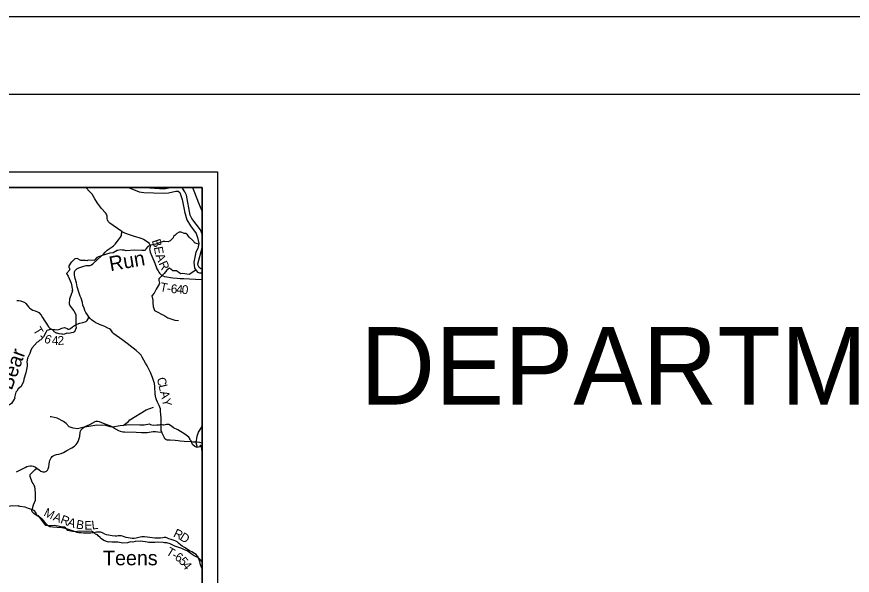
# Model space of a CAD drawing. Extents: x -1.8 to 75.7, y -2 to 25.
# Drawn here: x 7.7 to 13.09, y 18.4 to 22 of the extents above; entities that cross this region are included whole.
import ezdxf

# ---------------------------------------------------------------- set-up
doc = ezdxf.new("R2010")
doc.units = 0
for name, color, linetype in [('GM_X_County_Road', 7, 'Continuous'), ('GM_X_County_Road_Text', 7, 'Continuous'), ('GM_X_Major_River', 7, 'Continuous'), ('GM_X_Minor_River', 7, 'Continuous'), ('GM_X_Minor_River_Text', 7, 'Continuous'), ('GM_X_Township', 7, 'Continuous'), ('GM_X_Township_Road', 7, 'Continuous'), ('GM_X_Township_Road_Text', 7, 'Continuous'), ('SH_Border', 7, 'Continuous'), ('SH_Cut_Line', 7, 'Continuous'), ('SH_Data', 7, 'Continuous'), ('SH_Text', 7, 'Continuous')]:
    doc.layers.add(name, color=color, linetype=linetype)

msp = doc.modelspace()

# ---------------------------------------------------------------- linework, layer by layer
at = {"layer": 'GM_X_County_Road'}
for points in [[(8.6129, 19.5164), (8.6055, 19.5311), (8.6015, 19.5441), (8.599, 19.5551), (8.5975, 19.5698), (8.5969, 19.5817), (8.5961, 19.5989), (8.5961, 19.6158), (8.5931, 19.6351), (8.5804, 19.6748), (8.567, 19.7056), (8.5546, 19.7315), (8.5457, 19.7493), (8.5358, 19.7661), (8.5235, 19.7862), (8.5134, 19.806), (8.5065, 19.8173), (8.4965, 19.8297), (8.4756, 19.8483), (8.4163, 19.8946), (8.383, 19.9184), (8.3303, 19.9552), (8.3234, 19.9619), (8.3167, 19.9743), (8.3109, 19.9823), (8.3031, 19.9873), (8.2914, 19.9932), (8.2725, 20.0039), (8.2629, 20.0084), (8.2489, 20.0124), (8.2339, 20.018), (8.214, 20.0275), (8.2016, 20.0354), (8.187, 20.0465), (8.1786, 20.0544), (8.1698, 20.0651), (8.1612, 20.0781), (8.151, 20.0932), (8.1444, 20.1069), (8.139, 20.1218), (8.1318, 20.1417), (8.1296, 20.1583), (8.1206, 20.1847), (8.1145, 20.199), (8.1076, 20.2178), (8.0953, 20.2593), (8.0896, 20.2853), (8.0818, 20.3129), (8.0767, 20.3333), (8.0762, 20.3451), (8.0771, 20.3549), (8.0795, 20.3612), (8.0855, 20.3692), (8.0924, 20.3754), (8.105, 20.3804), (8.1372, 20.391), (8.1534, 20.3953), (8.1684, 20.3953), (8.1789, 20.3966), (8.1878, 20.4001), (8.1963, 20.407), (8.2252, 20.4344), (8.2635, 20.4703), (8.2756, 20.482), (8.2879, 20.4944), (8.3011, 20.5028), (8.3204, 20.5164), (8.3292, 20.5229), (8.3388, 20.5335), (8.3614, 20.5614), (8.3733, 20.5785), (8.3792, 20.5904), (8.3811, 20.5997), (8.3814, 20.6066), (8.3829, 20.6148), (8.3263, 20.6539), (8.3057, 20.6698), (8.2946, 20.6794), (8.2898, 20.6899), (8.2881, 20.6987), (8.2878, 20.7144), (8.2835, 20.7269), (8.2774, 20.7366), (8.2503, 20.7632), (8.2247, 20.7987), (8.2092, 20.8253), (8.1901, 20.8555), (8.1759, 20.8717), (8.1492, 20.8981), (8.1462, 20.9)], [(8.8374, 20.9), (8.8501, 20.8661), (8.8768, 20.801), (8.8876, 20.7751), (8.9, 20.7454)], [(8.6394, 19.3214), (8.6367, 19.3321), (8.6365, 19.345), (8.6371, 19.3758), (8.6371, 19.3978), (8.6363, 19.4149), (8.6342, 19.434), (8.6319, 19.4605), (8.631, 19.4721), (8.6285, 19.4834), (8.6239, 19.4945), (8.613, 19.5162), (8.6129, 19.5164)], [(8.9, 19.252), (8.8855, 19.2557), (8.8673, 19.2572), (8.8418, 19.2583), (8.8323, 19.2588), (8.7846, 19.2614), (8.7578, 19.2639), (8.7448, 19.2656), (8.726, 19.2675), (8.6935, 19.2695), (8.6826, 19.2698), (8.675, 19.2704), (8.6703, 19.272), (8.6652, 19.2749), (8.6602, 19.2798), (8.6573, 19.2858), (8.6518, 19.2992), (8.6479, 19.3076), (8.6428, 19.3152), (8.6394, 19.3214)]]:
    msp.add_lwpolyline(points, dxfattribs=at)
at = {"layer": 'GM_X_Major_River'}
msp.add_line((8.879, 20.5392), (8.8731, 20.5069), dxfattribs=at)
for points in [[(8.4305, 20.9), (8.4357, 20.8947), (8.4948, 20.8711), (8.5244, 20.8667), (8.6492, 20.8622)], [(8.6965, 20.9), (8.6834, 20.895), (8.6562, 20.888), (8.5635, 20.8954), (8.5137, 20.9)], [(8.6492, 20.8622), (8.6828, 20.865), (8.7304, 20.8759), (8.7448, 20.876), (8.7573, 20.867), (8.7708, 20.8211), (8.784, 20.7583), (8.7871, 20.7442), (8.8025, 20.6916), (8.8254, 20.6527), (8.8628, 20.602), (8.8701, 20.5763), (8.879, 20.5392)], [(8.9, 20.5978), (8.8999, 20.5985), (8.8887, 20.6253), (8.8331, 20.699), (8.8224, 20.7205), (8.7998, 20.8498), (8.7898, 20.8721), (8.7738, 20.894), (8.764, 20.9)], [(8.8731, 20.5069), (8.86, 20.4829), (8.846, 20.4172), (8.8507, 20.38), (8.8698, 20.3544), (8.8827, 20.3491), (8.8955, 20.3496), (8.9, 20.3501)], [(8.9, 20.3751), (8.8916, 20.3753), (8.881, 20.3844), (8.8749, 20.3957), (8.8733, 20.4079), (8.9, 20.5102)]]:
    msp.add_lwpolyline(points, dxfattribs=at)
at = {"layer": 'GM_X_Minor_River'}
for points in [[(8.8781, 20.5341), (8.8615, 20.5388), (8.8581, 20.5426), (8.8562, 20.5407), (8.8384, 20.5593), (8.8173, 20.5779), (8.8063, 20.593), (8.7957, 20.6036), (8.7843, 20.6036), (8.7658, 20.6112), (8.7522, 20.6108), (8.7363, 20.6035), (8.7269, 20.5925), (8.7152, 20.5837), (8.7129, 20.5753), (8.6956, 20.557), (8.694, 20.5551), (8.6804, 20.5479), (8.6596, 20.5516), (8.6491, 20.5501), (8.6011, 20.5336), (8.5697, 20.5282), (8.5497, 20.5179), (8.5387, 20.5065), (8.5319, 20.4936), (8.5115, 20.4931), (8.4631, 20.4953), (8.4098, 20.4899), (8.3981, 20.4955), (8.3841, 20.4948), (8.375, 20.4974), (8.3558, 20.4939), (8.3524, 20.4932), (8.3267, 20.4787), (8.3059, 20.4752), (8.256, 20.4599), (8.2209, 20.448), (8.2088, 20.4339), (8.2031, 20.4278), (8.1653, 20.4312), (8.1562, 20.4273), (8.1475, 20.4281), (8.1173, 20.4291), (8.0938, 20.4405), (8.0795, 20.4397), (8.0572, 20.4184), (8.0546, 20.4168), (8.0406, 20.3948), (8.041, 20.3834), (8.044, 20.3792), (8.0459, 20.3655), (8.0263, 20.3449), (8.0357, 20.3278), (8.0547, 20.2823), (8.0638, 20.2363), (8.0604, 20.2325), (8.0638, 20.2336), (8.0544, 20.2032), (8.0453, 20.1808), (8.0427, 20.1515), (8.0431, 20.1492), (8.0495, 20.134), (8.0738, 20.1048), (8.0866, 20.0801), (8.0866, 20.0554), (8.0863, 20.0064), (8.0871, 19.9954), (8.0769, 19.9684), (8.0675, 19.9649), (8.0391, 19.9588), (8.0274, 19.9595), (8.0127, 19.9545), (8.0002, 19.9518), (7.9987, 19.9545), (7.9775, 19.9552), (7.9658, 19.9601), (7.9609, 19.9605), (7.945, 19.9692), (7.9446, 19.973), (7.9321, 19.9829), (7.9234, 19.9847), (7.8996, 19.9778), (7.8913, 19.9641), (7.8777, 19.9364), (7.86, 19.9181), (7.8535, 19.9154), (7.8422, 19.9036), (7.8358, 19.9017), (7.8192, 19.8834), (7.8014, 19.8624), (7.7931, 19.8449), (7.7924, 19.8427), (7.7894, 19.8286), (7.7743, 19.7997), (7.7697, 19.7749), (7.7724, 19.7609), (7.7709, 19.7483), (7.763, 19.7042), (7.7498, 19.6628), (7.7476, 19.6487), (7.7329, 19.6164)], [(8.8606, 20.3667), (8.8168, 20.3392), (8.7738, 20.3443), (8.7632, 20.3416), (8.758, 20.3448), (8.7355, 20.3626), (8.7105, 20.3619), (8.6902, 20.3785), (8.6853, 20.3779), (8.6721, 20.3673), (8.6548, 20.3447), (8.6209, 20.3109), (8.6202, 20.2999), (8.6253, 20.2826), (8.6239, 20.2751), (8.6034, 20.2446), (8.6009, 20.2393), (8.5905, 20.2188), (8.5763, 20.2014), (8.5827, 20.1735), (8.5825, 20.1556), (8.5837, 20.1317), (8.5939, 20.1067), (8.6605, 20.0722), (8.6794, 20.0584), (8.7235, 20.044), (8.7473, 20.0418)], [(7.7329, 19.6164), (7.714, 19.6003), (7.7057, 19.5866), (7.6996, 19.5805), (7.6894, 19.5463), (7.6913, 19.5368), (7.6891, 19.5364), (7.6887, 19.5345), (7.6706, 19.5071), (7.6585, 19.498), (7.6264, 19.4952), (7.6169, 19.491), (7.5984, 19.4876), (7.5791, 19.4906), (7.5663, 19.4886), (7.5447, 19.4821)], [(8.392, 19.3653), (8.4259, 19.3897), (8.4331, 19.4024), (8.5389, 19.4659), (8.5859, 19.483)], [(8.3714, 19.3637), (8.3227, 19.3535), (8.3077, 19.3555), (8.2793, 19.3659), (8.2222, 19.3678), (8.1314, 19.3513), (8.0964, 19.3437), (8.0678, 19.3476), (8.0431, 19.3564), (8.0225, 19.3768), (8.0063, 19.3906), (7.9651, 19.4132), (7.9259, 19.4198), (7.92, 19.4203)], [(8.9, 19.2049), (8.898, 19.2055), (8.8987, 19.2085), (8.8991, 19.2161), (8.8915, 19.2362), (8.8866, 19.2355), (8.8847, 19.2309), (8.8832, 19.2282), (8.8677, 19.2233), (8.8537, 19.2293), (8.8371, 19.2422), (8.8295, 19.2661), (8.8219, 19.2737), (8.8215, 19.2802), (8.8147, 19.2897), (8.7882, 19.309), (8.7432, 19.3363), (8.7167, 19.3495), (8.7031, 19.3601), (8.685, 19.3715), (8.6714, 19.3714), (8.654, 19.3668), (8.6513, 19.3676), (8.6351, 19.3714), (8.6233, 19.3671), (8.6086, 19.3679), (8.5855, 19.3659), (8.5682, 19.3701), (8.5602, 19.3735), (8.5273, 19.3669), (8.4982, 19.3665), (8.4336, 19.3686), (8.3707, 19.3635)], [(8.8694, 19.2238), (8.8614, 19.2535), (8.8672, 19.2966), (8.8771, 19.3229), (8.9, 19.3595)], [(7.8346, 18.7875), (7.8274, 18.8035), (7.8164, 18.8179), (7.7805, 18.8304), (7.7586, 18.8383), (7.7276, 18.842), (7.7208, 18.8454), (7.7162, 18.8462), (7.7132, 18.8443), (7.6796, 18.8476), (7.6614, 18.8453), (7.6437, 18.8411), (7.6274, 18.8425), (7.6006, 18.8398), (7.5749, 18.8398), (7.5507, 18.8317), (7.5401, 18.8351), (7.5284, 18.8366), (7.5136, 18.8237), (7.4785, 18.8088), (7.4755, 18.8076), (7.4301, 18.7798), (7.4154, 18.7714)], [(8.9, 18.4865), (8.8915, 18.4976), (8.8771, 18.5117), (8.848, 18.5257), (8.8363, 18.5344), (8.8041, 18.556), (8.786, 18.5632), (8.7689, 18.5722), (8.7243, 18.5877), (8.6933, 18.6017), (8.6721, 18.6085), (8.6574, 18.6096), (8.6498, 18.6104), (8.6098, 18.6137), (8.5943, 18.6118), (8.5568, 18.6101), (8.5345, 18.615), (8.4997, 18.6203), (8.4691, 18.6179), (8.4532, 18.6137), (8.4374, 18.614), (8.4192, 18.6083), (8.3886, 18.6063), (8.3569, 18.612), (8.3172, 18.6126), (8.3032, 18.6156), (8.2971, 18.6137), (8.2654, 18.6235), (8.2442, 18.6387), (8.2423, 18.6436), (8.229, 18.6535), (8.2264, 18.6596), (8.2124, 18.6648), (8.2071, 18.6709), (8.1867, 18.6838), (8.156, 18.6811), (8.1103, 18.6829), (8.0831, 18.6801), (8.0642, 18.6809), (8.0336, 18.6888), (8.0241, 18.7013), (8.0199, 18.7051), (8.012, 18.7096), (7.9995, 18.7092), (7.9708, 18.7171), (7.9462, 18.7201), (7.9107, 18.7174), (7.8929, 18.7204), (7.8694, 18.7534), (7.8448, 18.7818), (7.8346, 18.7875)]]:
    msp.add_lwpolyline(points, dxfattribs=at)
at = {"layer": 'GM_X_Township'}
msp.add_lwpolyline([(8.9, 17.0276), (8.9, 20.9), (6.4874, 20.9)], dxfattribs=at)
at = {"layer": 'GM_X_Township_Road'}
for points in [[(8.3829, 20.6148), (8.4002, 20.6074), (8.43, 20.5968), (8.4564, 20.5878), (8.4765, 20.5817), (8.4921, 20.577), (8.5107, 20.5702), (8.5228, 20.5661), (8.5334, 20.5594), (8.5543, 20.5445), (8.5593, 20.5378), (8.5636, 20.5289), (8.5643, 20.5209), (8.5626, 20.5095), (8.5612, 20.5006), (8.5621, 20.4935), (8.5647, 20.4822), (8.5751, 20.4564), (8.5943, 20.4115), (8.6088, 20.3754), (8.6158, 20.3612), (8.6203, 20.3534), (8.6255, 20.3467), (8.6318, 20.3395), (8.6376, 20.3339), (8.6458, 20.3287), (8.6566, 20.3257), (8.6722, 20.3231), (8.6973, 20.3191)], [(8.6973, 20.3191), (8.712, 20.3168), (8.7392, 20.3142), (8.7591, 20.3125), (8.7816, 20.3116), (8.8179, 20.3095), (8.8581, 20.3088), (8.9, 20.3068)], [(7.7042, 20.1705), (7.7184, 20.171), (7.7293, 20.1694), (7.7428, 20.1648), (7.7559, 20.1579), (7.7641, 20.1524), (7.7722, 20.1415), (7.7807, 20.1309), (7.7878, 20.1229), (7.7979, 20.1147), (7.8084, 20.1092), (7.8225, 20.1041), (7.838, 20.0985), (7.8464, 20.093), (7.8615, 20.0757), (7.8717, 20.0613), (7.8864, 20.0383), (7.8996, 20.0175), (7.9091, 20.0015), (7.9187, 19.9922), (7.9253, 19.9873), (7.9379, 19.9838), (7.951, 19.9827), (7.9683, 19.9822), (7.9831, 19.9862), (7.996, 19.9913), (8.0042, 19.9955), (8.0128, 19.9969), (8.0201, 19.9953), (8.0294, 19.9893), (8.0369, 19.9858), (8.0429, 19.9853), (8.0504, 19.9893), (8.0653, 20.0015), (8.0779, 20.0088), (8.0952, 20.0177), (8.1125, 20.0246), (8.1311, 20.029), (8.1466, 20.0334), (8.1537, 20.0372), (8.1592, 20.0416), (8.1647, 20.0531), (8.1698, 20.0651)], [(7.7029, 19.0665), (7.7369, 19.0841), (7.7582, 19.0946), (7.7705, 19.1004), (7.7789, 19.1029), (7.7921, 19.1052), (7.8, 19.1046), (7.8098, 19.1032), (7.8252, 19.0963), (7.8344, 19.0893), (7.8397, 19.0861), (7.8485, 19.0783), (7.8594, 19.0709), (7.8667, 19.0674), (7.8723, 19.0662), (7.8779, 19.0659), (7.8865, 19.0667), (7.8916, 19.0684), (7.8972, 19.0712), (7.9023, 19.0771), (7.907, 19.085), (7.9115, 19.0979), (7.9137, 19.1153), (7.916, 19.1301), (7.9191, 19.1391), (7.9275, 19.1562), (7.9331, 19.1643), (7.9393, 19.1699), (7.9485, 19.1741), (7.9617, 19.1779), (7.9752, 19.1793), (7.9915, 19.1845), (8.0058, 19.1912), (8.0285, 19.2041), (8.0601, 19.2201), (8.0764, 19.2324), (8.0871, 19.2414), (8.0948, 19.2507), (8.1017, 19.2627), (8.1077, 19.2802), (8.1111, 19.297), (8.1136, 19.3194), (8.116, 19.3279), (8.119, 19.3359), (8.1234, 19.3419), (8.133, 19.3495), (8.1425, 19.3562), (8.1551, 19.3626), (8.1765, 19.3722), (8.2113, 19.3903), (8.2168, 19.3926), (8.2214, 19.3935), (8.227, 19.3935), (8.2359, 19.3915), (8.2726, 19.3764), (8.3094, 19.3624), (8.3212, 19.3564), (8.3424, 19.3443), (8.3602, 19.3332), (8.3713, 19.3286), (8.38, 19.3259), (8.3891, 19.3247), (8.4005, 19.3237), (8.4746, 19.3225), (8.5095, 19.3206), (8.5293, 19.3203), (8.5466, 19.3208), (8.5711, 19.3242), (8.5855, 19.3264), (8.599, 19.327), (8.6142, 19.3251), (8.6394, 19.3214)], [(8.9, 18.4451), (8.8949, 18.4551), (8.8897, 18.4677), (8.8848, 18.4875), (8.8771, 18.5101), (8.8738, 18.5186), (8.8693, 18.5252), (8.861, 18.533), (8.8501, 18.5402), (8.833, 18.5499), (8.8186, 18.5577), (8.804, 18.5669), (8.7867, 18.5781), (8.7713, 18.5881), (8.7624, 18.5945), (8.7472, 18.6069), (8.7388, 18.6141), (8.7316, 18.6188), (8.7198, 18.6235), (8.7003, 18.6295), (8.6859, 18.6351), (8.6737, 18.6402), (8.6659, 18.6421), (8.656, 18.6425), (8.6458, 18.6412), (8.6324, 18.6396), (8.6182, 18.6396), (8.5945, 18.6385), (8.5624, 18.6435), (8.5285, 18.6472), (8.5171, 18.648), (8.5115, 18.6472), (8.5017, 18.6455), (8.4824, 18.6406), (8.4749, 18.6385), (8.4614, 18.6365), (8.4488, 18.6367), (8.4224, 18.6398), (8.4095, 18.6421), (8.3984, 18.6468), (8.3867, 18.6515), (8.378, 18.6532), (8.3677, 18.654), (8.3595, 18.6532), (8.3504, 18.6517), (8.3391, 18.6517), (8.321, 18.6536), (8.2967, 18.6575), (8.2831, 18.6612), (8.2735, 18.6655), (8.2568, 18.6727), (8.2445, 18.6764), (8.2313, 18.6774), (8.2189, 18.6768), (8.2017, 18.6735), (8.1833, 18.6717), (8.1722, 18.6719), (8.1571, 18.6715), (8.135, 18.6719), (8.1206, 18.6725), (8.1047, 18.6737), (8.0935, 18.6753), (8.0713, 18.6837), (8.0512, 18.6902), (8.0316, 18.6961), (8.0163, 18.7009), (8.0057, 18.704), (7.9953, 18.7056), (7.9654, 18.7074), (7.9364, 18.7092), (7.9239, 18.7107), (7.9191, 18.7116), (7.9141, 18.7134), (7.9076, 18.7182), (7.9001, 18.7249), (7.8927, 18.7329), (7.886, 18.7411), (7.8787, 18.7499), (7.8729, 18.757), (7.8571, 18.7702), (7.8509, 18.7747), (7.8374, 18.7836), (7.8231, 18.7915), (7.8142, 18.7987), (7.8092, 18.804), (7.8046, 18.8088), (7.8016, 18.8142), (7.8018, 18.8195), (7.8053, 18.8299), (7.8123, 18.8526), (7.8246, 18.8845), (7.826, 18.8949), (7.8266, 18.9008), (7.8255, 18.928), (7.8231, 18.9518), (7.8207, 18.9708), (7.8176, 18.9784), (7.81, 18.9906), (7.8044, 18.9989), (7.8018, 19.0056), (7.7934, 19.029), (7.791, 19.037), (7.7906, 19.0447), (7.7915, 19.0497), (7.7952, 19.0542), (7.8092, 19.0673), (7.822, 19.0786), (7.8344, 19.0893)]]:
    msp.add_lwpolyline(points, dxfattribs=at)
at = {"layer": 'SH_Border'}
msp.add_lwpolyline([(1.5, 21.5), (33.5, 21.5), (33.5, 0.5), (1.5, 0.5)], close=True, dxfattribs=at)
at = {"layer": 'SH_Cut_Line'}
msp.add_lwpolyline([(0, 0), (34, 0), (34, 22), (0, 22)], close=True, dxfattribs=at)
at = {"layer": 'SH_Data'}
for p, q in [((2, 21), (9, 21)), ((9, 21), (9, 14)), ((2.1, 20.9), (8.9, 20.9)), ((8.9, 20.9), (8.9, 14.1))]:
    msp.add_line(p, q, dxfattribs=at)

# ---------------------------------------------------------------- texts
at = {"layer": 'GM_X_County_Road_Text'}
for s, rotation, p in [('C', 284.8811, (8.6066, 19.6674)), ('L', 283.4116, (8.6185, 19.6227)), ('A', 283.2649, (8.6283, 19.5814)), ('Y', 282.2601, (8.6398, 19.533))]:
    msp.add_text(s, height=0.0568, rotation=rotation, dxfattribs=at).set_placement(p)
at = {"layer": 'GM_X_Minor_River_Text'}
for s, rotation, p in [('Run', 9.9969, (8.3087, 20.359)), ('Bear', 69.9999, (7.6719, 19.5877)), ('Teens', 359.9977, (8.2613, 18.4637))]:
    msp.add_text(s, height=0.0947, rotation=rotation, dxfattribs=at).set_placement(p)
at = {"layer": 'GM_X_Township_Road_Text'}
for s, rotation, p in [('B', 288.0968, (8.5747, 20.5562)), ('E', 280.0193, (8.5887, 20.5139)), ('A', 290.6476, (8.5991, 20.461)), ('R', 294.8309, (8.6185, 20.41)), ('T', 348.6048, (8.625, 20.2326)), ('6', 354.6585, (8.6962, 20.2198)), ('4', 355.9016, (8.7324, 20.2164)), ('0', 356.0397, (8.7674, 20.2139)), ('-', 351.4113, (8.6696, 20.2237)), ('T', 301.8153, (7.8074, 19.9798)), ('-', 317.7887, (7.8408, 19.9304)), ('6', 337.7004, (7.8762, 19.9033)), ('4', 358.6796, (7.9307, 19.8854)), ('2', 1.2166, (7.9684, 19.8846)), ('M', 333.3729, (7.8739, 18.7855)), ('A', 338.7437, (7.9343, 18.7555)), ('R', 339.4844, (7.9817, 18.7371)), ('A', 341.4264, (8.0273, 18.72)), ('B', 350.1678, (8.0839, 18.7018)), ('E', 0.9004, (8.1415, 18.6929)), ('L', 6.9711, (8.1905, 18.694)), ('R', 334.7983, (8.7103, 18.6507)), ('D', 327.6008, (8.7508, 18.6317)), ('T', 329.1935, (8.6631, 18.5361)), ('6', 329.1697, (8.7196, 18.5024)), ('-', 329.1895, (8.6996, 18.5144)), ('5', 310.971, (8.746, 18.4875)), ('4', 308.1819, (8.7685, 18.4617))]:
    msp.add_text(s, height=0.0568, rotation=rotation, dxfattribs=at).set_placement(p)
at = {"layer": 'SH_Text'}
msp.add_text('DEPARTMENT OF TRANSPORTATION', height=0.5, dxfattribs=at).set_placement((9.9196, 19.5))

doc.saveas('drawing.dxf')
